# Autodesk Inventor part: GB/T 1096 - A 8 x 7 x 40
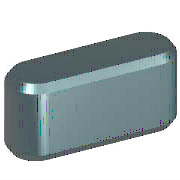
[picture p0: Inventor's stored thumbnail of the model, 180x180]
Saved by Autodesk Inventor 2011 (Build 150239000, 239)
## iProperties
Created: 2010-02
Part Number: GB/T 1096 - A 8 x 7 x 40
Material: 低炭钢
Description: 方形键和矩形键
Document SubType Name: Modeling
Standard: GB/T 1096-2003
Designer: Administrator
Standard Revision: 2003
Standards Organization: GB
Language: zh-CN
Size Designation: A 8 x 7 x 40
Categories: <MemberInstance><Categories><Category DisplayName="轴用零件" InternalName="7f7aeb1f-a693-4053-b835-cee3144e0d98" Mnemonic="SHFT"><Category DisplayName="键" InternalN
Density: 1 g/cm^3
IsCustomPart: 1
Author: Administrator
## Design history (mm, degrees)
sketch "Sketch1"
  geometry: L1 (4, 4)-(36, 4); L2 (36, -4)-(4, -4); L3 (0, 9.4)-(0, -7.4) reference; L4 (-5, 0)-(30, 0) reference; L5 (40, 0)-(40, 7); A1 r 4 centre (4, 0) between (4, 4) and (4, -4); A2 r 4 centre (36, 0) between (36, -4) and (36, 4)
  constraints: 6 end point, 5 point on circle, 4 tangent, 3 point on line, 2 centre point, 1 horizontal, 1 parallel, 1 perpendicular
  dimensions: "d0" = 4 radius of A1 (= 0.5 x PB); "d13" = 4 radius of A2 (= 0.5 x PB); "d14" = 40 distance between parallel lines of L5 L3 (= NLG)
workplane "Work Plane1"
workplane "Work Plane2"
extrude "Body1" new body sketch "Sketch1" taper "d3" = 0 deg; stored distance "d4" = 10
chamfer "Chamfer1" distance "d8" = 0.4 (= PHH); stored, may be unused: second distance "d9" = 0.4 (= PHH), angle "d15" = 45 deg
workplane "Work Plane3"
body "Solid1"
other parameters: "d1" = -4 (= -PNT), "d2" = 3 (= PH - PNT), "NLG" = 40 [user parameter; used in 1 equation term], "PB" = 8 [user parameter; used in 2 equation terms], "PNT" = 4 [user parameter; used in 2 equation terms], "PH" = 7 [user parameter; used in 1 equation term], "PHH" = 0.4 [user parameter; used in 2 equation terms], "d10" = 0, "d16" = 0, "d17" = 0, "d18" = 0, "WDMIN" = 22 [user parameter], "PLB2" = 48 [user parameter], "PLB1" = 44 [user parameter], "RR" = 0.16 [user parameter], "PUEB" = 3.3 [user parameter], "c1" = 0 [user parameter], "THREADDIA" = 0 [user parameter], "PTC" = 0 [user parameter]
